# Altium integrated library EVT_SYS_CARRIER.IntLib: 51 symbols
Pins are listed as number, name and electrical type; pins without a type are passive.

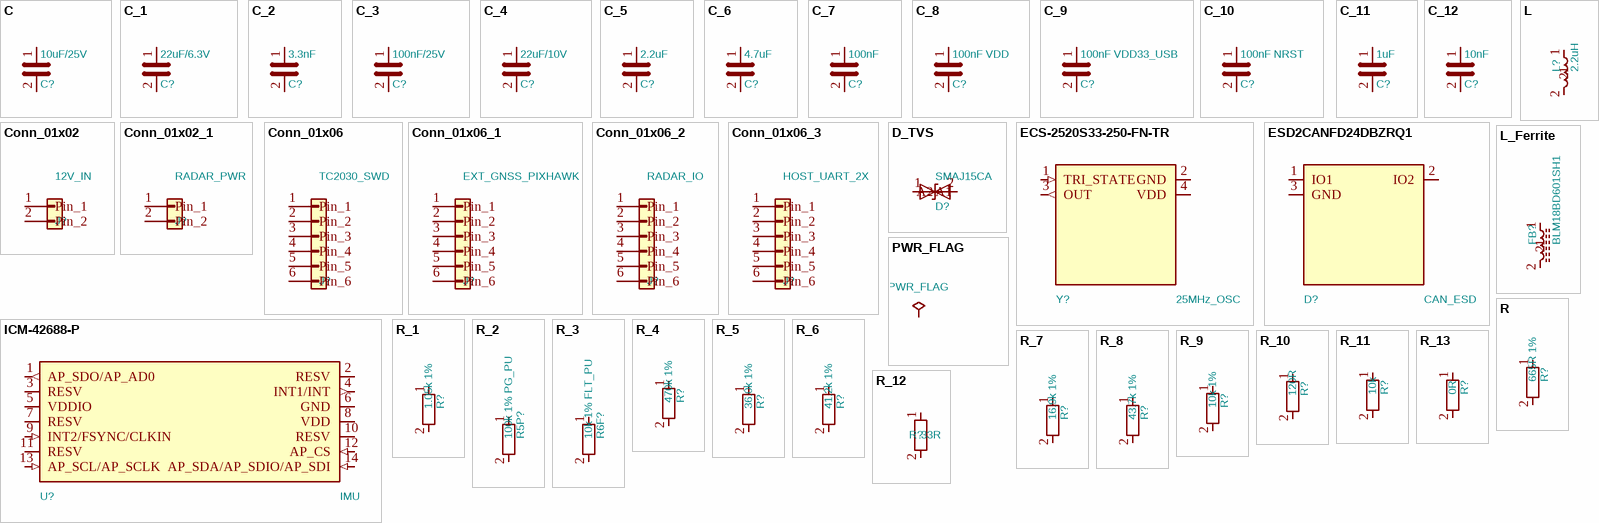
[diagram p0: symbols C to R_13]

## C
designator C?, comment 10uF/25V
MPN: 10uF_25V_X7R; hierarchy_path: /9ce958f3-6019-45fe-bc02-0cccce48adf8/8ef865ad-b15f-47f6-9f00-bb693d917fe2
footprint C_1206_3216Metric
pins: 1, 2

## C_1
designator C?, comment 22uF/6.3V
MPN: 22uF_6.3V_X7R; hierarchy_path: /9ce958f3-6019-45fe-bc02-0cccce48adf8/8ef865ad-b15f-47f6-9f00-bb693d917fe2
footprint C_1206_3216Metric
pins: 1, 2

## C_2
designator C?, comment 3.3nF
MPN: 3.3nF_X7R; hierarchy_path: /9ce958f3-6019-45fe-bc02-0cccce48adf8/8ef865ad-b15f-47f6-9f00-bb693d917fe2
footprint C_0603_1608Metric
pins: 1, 2

## C_3
designator C?, comment 100nF/25V
MPN: 100nF_25V_X7R; hierarchy_path: /9ce958f3-6019-45fe-bc02-0cccce48adf8/8ef865ad-b15f-47f6-9f00-bb693d917fe2
footprint C_0603_1608Metric
pins: 1, 2

## C_4
designator C?, comment 22uF/10V
MPN: 22uF_10V_X7R; hierarchy_path: /9ce958f3-6019-45fe-bc02-0cccce48adf8/8ef865ad-b15f-47f6-9f00-bb693d917fe2
footprint C_1206_3216Metric
pins: 1, 2

## C_5
designator C?, comment 2.2uF
MPN: 2.2uF_6.3V_X7R; hierarchy_path: /9ce958f3-6019-45fe-bc02-0cccce48adf8/eca40e6c-42e8-40ce-997d-d3259c6d70bc
footprint C_0603_1608Metric
pins: 1, 2

## C_6
designator C?, comment 4.7uF
MPN: 4.7uF_6.3V_X7R; hierarchy_path: /9ce958f3-6019-45fe-bc02-0cccce48adf8/eca40e6c-42e8-40ce-997d-d3259c6d70bc
footprint C_0805_2012Metric
pins: 1, 2

## C_7
designator C?, comment 100nF
MPN: 100nF_6.3V_X7R; hierarchy_path: /9ce958f3-6019-45fe-bc02-0cccce48adf8/eca40e6c-42e8-40ce-997d-d3259c6d70bc
footprint C_0402_1005Metric
pins: 1, 2

## C_8
designator C?, comment 100nF VDD
MPN: 100nF_6.3V_X7R; Decouples_U1_Pin: 15; hierarchy_path: /9ce958f3-6019-45fe-bc02-0cccce48adf8/eca40e6c-42e8-40ce-997d-d3259c6d70bc
footprint C_0402_1005Metric
pins: 1, 2

## C_9
designator C?, comment 100nF VDD33_USB
MPN: 100nF_6.3V_X7R; Decouples_U1_Pin: 114; hierarchy_path: /9ce958f3-6019-45fe-bc02-0cccce48adf8/eca40e6c-42e8-40ce-997d-d3259c6d70bc
footprint C_0402_1005Metric
pins: 1, 2

## C_10
designator C?, comment 100nF NRST
MPN: 100nF_6.3V_X7R; Filters_U1_Pin: 31; hierarchy_path: /9ce958f3-6019-45fe-bc02-0cccce48adf8/eca40e6c-42e8-40ce-997d-d3259c6d70bc
footprint C_0402_1005Metric
pins: 1, 2

## C_11
designator C?, comment 1uF
MPN: 1uF_6.3V_X7R; hierarchy_path: /9ce958f3-6019-45fe-bc02-0cccce48adf8/eca40e6c-42e8-40ce-997d-d3259c6d70bc
footprint C_0603_1608Metric
pins: 1, 2

## C_12
designator C?, comment 10nF
MPN: 10nF_6.3V_X7R; hierarchy_path: /9ce958f3-6019-45fe-bc02-0cccce48adf8/241b9f8d-0f6d-4c6e-8897-d9638f4bbe65
footprint C_0402_1005Metric
pins: 1, 2

## Conn_01x02
designator J?, comment 12V_IN
MPN: 43650-0200; hierarchy_path: /9ce958f3-6019-45fe-bc02-0cccce48adf8/8ef865ad-b15f-47f6-9f00-bb693d917fe2
footprint Molex_43650-0200_RA_THT_2P
pins: 1 Pin_1, 2 Pin_2

## Conn_01x02_1
designator J?, comment RADAR_PWR
MPN: 43650-0200; hierarchy_path: /9ce958f3-6019-45fe-bc02-0cccce48adf8/4586aff2-28b2-41d1-b1d0-d420a17fa486
footprint Molex_43650-0200_RA_THT_2P
pins: 1 Pin_1, 2 Pin_2

## Conn_01x06
designator J?, comment TC2030_SWD
MPN: TC2030-NL_TARGET; hierarchy_path: /9ce958f3-6019-45fe-bc02-0cccce48adf8/eca40e6c-42e8-40ce-997d-d3259c6d70bc
footprint TagConnect_TC2030_NL
pins: 1 Pin_1, 2 Pin_2, 3 Pin_3, 4 Pin_4, 5 Pin_5, 6 Pin_6

## Conn_01x06_1
designator J?, comment EXT_GNSS_PIXHAWK
MPN: SM06B-GHS-TB(LF)(SN); hierarchy_path: /9ce958f3-6019-45fe-bc02-0cccce48adf8/f1a35d3c-9d0c-4b86-b39c-b974cbb805b6
footprint JST_GH_SM06B-GHS-TB_1x06-1MP_P1.25mm_Horizontal
pins: 1 Pin_1, 2 Pin_2, 3 Pin_3, 4 Pin_4, 5 Pin_5, 6 Pin_6

## Conn_01x06_2
designator J?, comment RADAR_IO
MPN: 43045-0600; hierarchy_path: /9ce958f3-6019-45fe-bc02-0cccce48adf8/4586aff2-28b2-41d1-b1d0-d420a17fa486
footprint Molex_43045-0600_RA_THT_6P
pins: 1 Pin_1, 2 Pin_2, 3 Pin_3, 4 Pin_4, 5 Pin_5, 6 Pin_6

## Conn_01x06_3
designator J?, comment HOST_UART_2X
MPN: 43045-0600; hierarchy_path: /9ce958f3-6019-45fe-bc02-0cccce48adf8/2832ddd1-de9d-48ab-8137-5ba09d30c47d
footprint Molex_43045-0600_RA_THT_6P
pins: 1 Pin_1, 2 Pin_2, 3 Pin_3, 4 Pin_4, 5 Pin_5, 6 Pin_6

## D_TVS
designator D?, comment SMAJ15CA
hierarchy_path: /9ce958f3-6019-45fe-bc02-0cccce48adf8/8ef865ad-b15f-47f6-9f00-bb693d917fe2
footprint D_SMA
pins: 1 A1, 2 A2

## ECS-2520S33-250-FN-TR
designator Y?, comment 25MHz_OSC
MPN: ECS-2520S33-250-FN-TR; Capture_Status: LOCAL_CONTRACT_SYMBOL; hierarchy_path: /9ce958f3-6019-45fe-bc02-0cccce48adf8/eca40e6c-42e8-40ce-997d-d3259c6d70bc
footprint Oscillator_SMD_ECS_2520MV-xxx-xx-4Pin_2.5x2.0mm
pins: 1 TRI_STATE (in), 2 GND (power), 3 OUT (out), 4 VDD (power)

## ESD2CANFD24DBZRQ1
designator D?, comment CAN_ESD
MPN: ESD2CANFD24DBZRQ1; Capture_Status: LOCAL_CONTRACT_SYMBOL; hierarchy_path: /9ce958f3-6019-45fe-bc02-0cccce48adf8/4586aff2-28b2-41d1-b1d0-d420a17fa486
footprint SOT-23
pins: 1 IO1 (io), 2 IO2 (io), 3 GND

## ICM-42688-P
designator U?, comment IMU
MPN: ICM-42688-P; Capture_Status: LOCAL_CONTRACT_SYMBOL; hierarchy_path: /9ce958f3-6019-45fe-bc02-0cccce48adf8/241b9f8d-0f6d-4c6e-8897-d9638f4bbe65
footprint ICM-42688-P_LGA14_2.5x3mm_P0.5mm
pins: 1 AP_SDO/AP_AD0 (out), 2 RESV, 3 RESV, 4 INT1/INT (out), 5 VDDIO (power), 6 GND (power), 7 RESV, 8 VDD (power), 9 INT2/FSYNC/CLKIN (in), 10 RESV, 11 RESV, 12 AP_CS (in), 13 AP_SCL/AP_SCLK (in), 14 AP_SDA/AP_SDIO/AP_SDI (in)

## L
designator L?, comment 2.2uH
MPN: XFL4020-222MEC; hierarchy_path: /9ce958f3-6019-45fe-bc02-0cccce48adf8/8ef865ad-b15f-47f6-9f00-bb693d917fe2
footprint Coilcraft_XFL4020_4x4
pins: 1, 2

## L_Ferrite
designator FB?, comment BLM18BD601SH1
hierarchy_path: /9ce958f3-6019-45fe-bc02-0cccce48adf8/eca40e6c-42e8-40ce-997d-d3259c6d70bc
footprint L_0603_1608Metric
pins: 1, 2

## PWR_FLAG
designator #FLG?  (graphical)
hierarchy_path: /9ce958f3-6019-45fe-bc02-0cccce48adf8/8ef865ad-b15f-47f6-9f00-bb693d917fe2
pins: 1 (power)

## R
designator R?, comment 665R 1%
MPN: 665R_1%; hierarchy_path: /9ce958f3-6019-45fe-bc02-0cccce48adf8/8ef865ad-b15f-47f6-9f00-bb693d917fe2
footprint R_0603_1608Metric
pins: 1, 2

## R_1
designator R?, comment 1.05k 1%
MPN: 1.05k_1%; hierarchy_path: /9ce958f3-6019-45fe-bc02-0cccce48adf8/8ef865ad-b15f-47f6-9f00-bb693d917fe2
footprint R_0603_1608Metric
pins: 1, 2

## R_2
designator R5P?, comment 100k 1% PG_PU
MPN: 100k_1%; hierarchy_path: /9ce958f3-6019-45fe-bc02-0cccce48adf8/8ef865ad-b15f-47f6-9f00-bb693d917fe2
footprint R_0603_1608Metric
pins: 1, 2

## R_3
designator R6F?, comment 10k 1% FLT_PU
MPN: 10k_1%; hierarchy_path: /9ce958f3-6019-45fe-bc02-0cccce48adf8/8ef865ad-b15f-47f6-9f00-bb693d917fe2
footprint R_0603_1608Metric
pins: 1, 2

## R_4
designator R?, comment 470k 1%
MPN: 470k_1%; hierarchy_path: /9ce958f3-6019-45fe-bc02-0cccce48adf8/8ef865ad-b15f-47f6-9f00-bb693d917fe2
footprint R_0603_1608Metric
pins: 1, 2

## R_5
designator R?, comment 36.0k 1%
MPN: 36.0k_1%; hierarchy_path: /9ce958f3-6019-45fe-bc02-0cccce48adf8/8ef865ad-b15f-47f6-9f00-bb693d917fe2
footprint R_0603_1608Metric
pins: 1, 2

## R_6
designator R?, comment 41.2k 1%
MPN: 41.2k_1%; hierarchy_path: /9ce958f3-6019-45fe-bc02-0cccce48adf8/8ef865ad-b15f-47f6-9f00-bb693d917fe2
footprint R_0603_1608Metric
pins: 1, 2

## R_7
designator R?, comment 16.9k 1%
MPN: 16.9k_1%; hierarchy_path: /9ce958f3-6019-45fe-bc02-0cccce48adf8/8ef865ad-b15f-47f6-9f00-bb693d917fe2
footprint R_0603_1608Metric
pins: 1, 2

## R_8
designator R?, comment 43.7k 1%
MPN: 43.7k_1%; hierarchy_path: /9ce958f3-6019-45fe-bc02-0cccce48adf8/8ef865ad-b15f-47f6-9f00-bb693d917fe2
footprint R_0603_1608Metric
pins: 1, 2

## R_9
designator R?, comment 10k 1%
MPN: 10k_1%; hierarchy_path: /9ce958f3-6019-45fe-bc02-0cccce48adf8/eca40e6c-42e8-40ce-997d-d3259c6d70bc
footprint R_0603_1608Metric
pins: 1, 2

## R_10
designator R?, comment 120R
MPN: 120R_1%; hierarchy_path: /9ce958f3-6019-45fe-bc02-0cccce48adf8/4586aff2-28b2-41d1-b1d0-d420a17fa486
footprint R_0603_1608Metric
pins: 1, 2

## R_11
designator R?, comment 10k
MPN: 10k_1%; hierarchy_path: /9ce958f3-6019-45fe-bc02-0cccce48adf8/4586aff2-28b2-41d1-b1d0-d420a17fa486
footprint R_0603_1608Metric
pins: 1, 2

## R_12
designator R?, comment 33R
MPN: 33R_1%; hierarchy_path: /9ce958f3-6019-45fe-bc02-0cccce48adf8/2832ddd1-de9d-48ab-8137-5ba09d30c47d
footprint R_0402_1005Metric
pins: 1, 2

## R_13
designator R?, comment 0R
hierarchy_path: /9ce958f3-6019-45fe-bc02-0cccce48adf8/6cb1464a-bb78-4666-9d5a-fa6b793f4d4c
footprint R_0603_1608Metric
pins: 1, 2

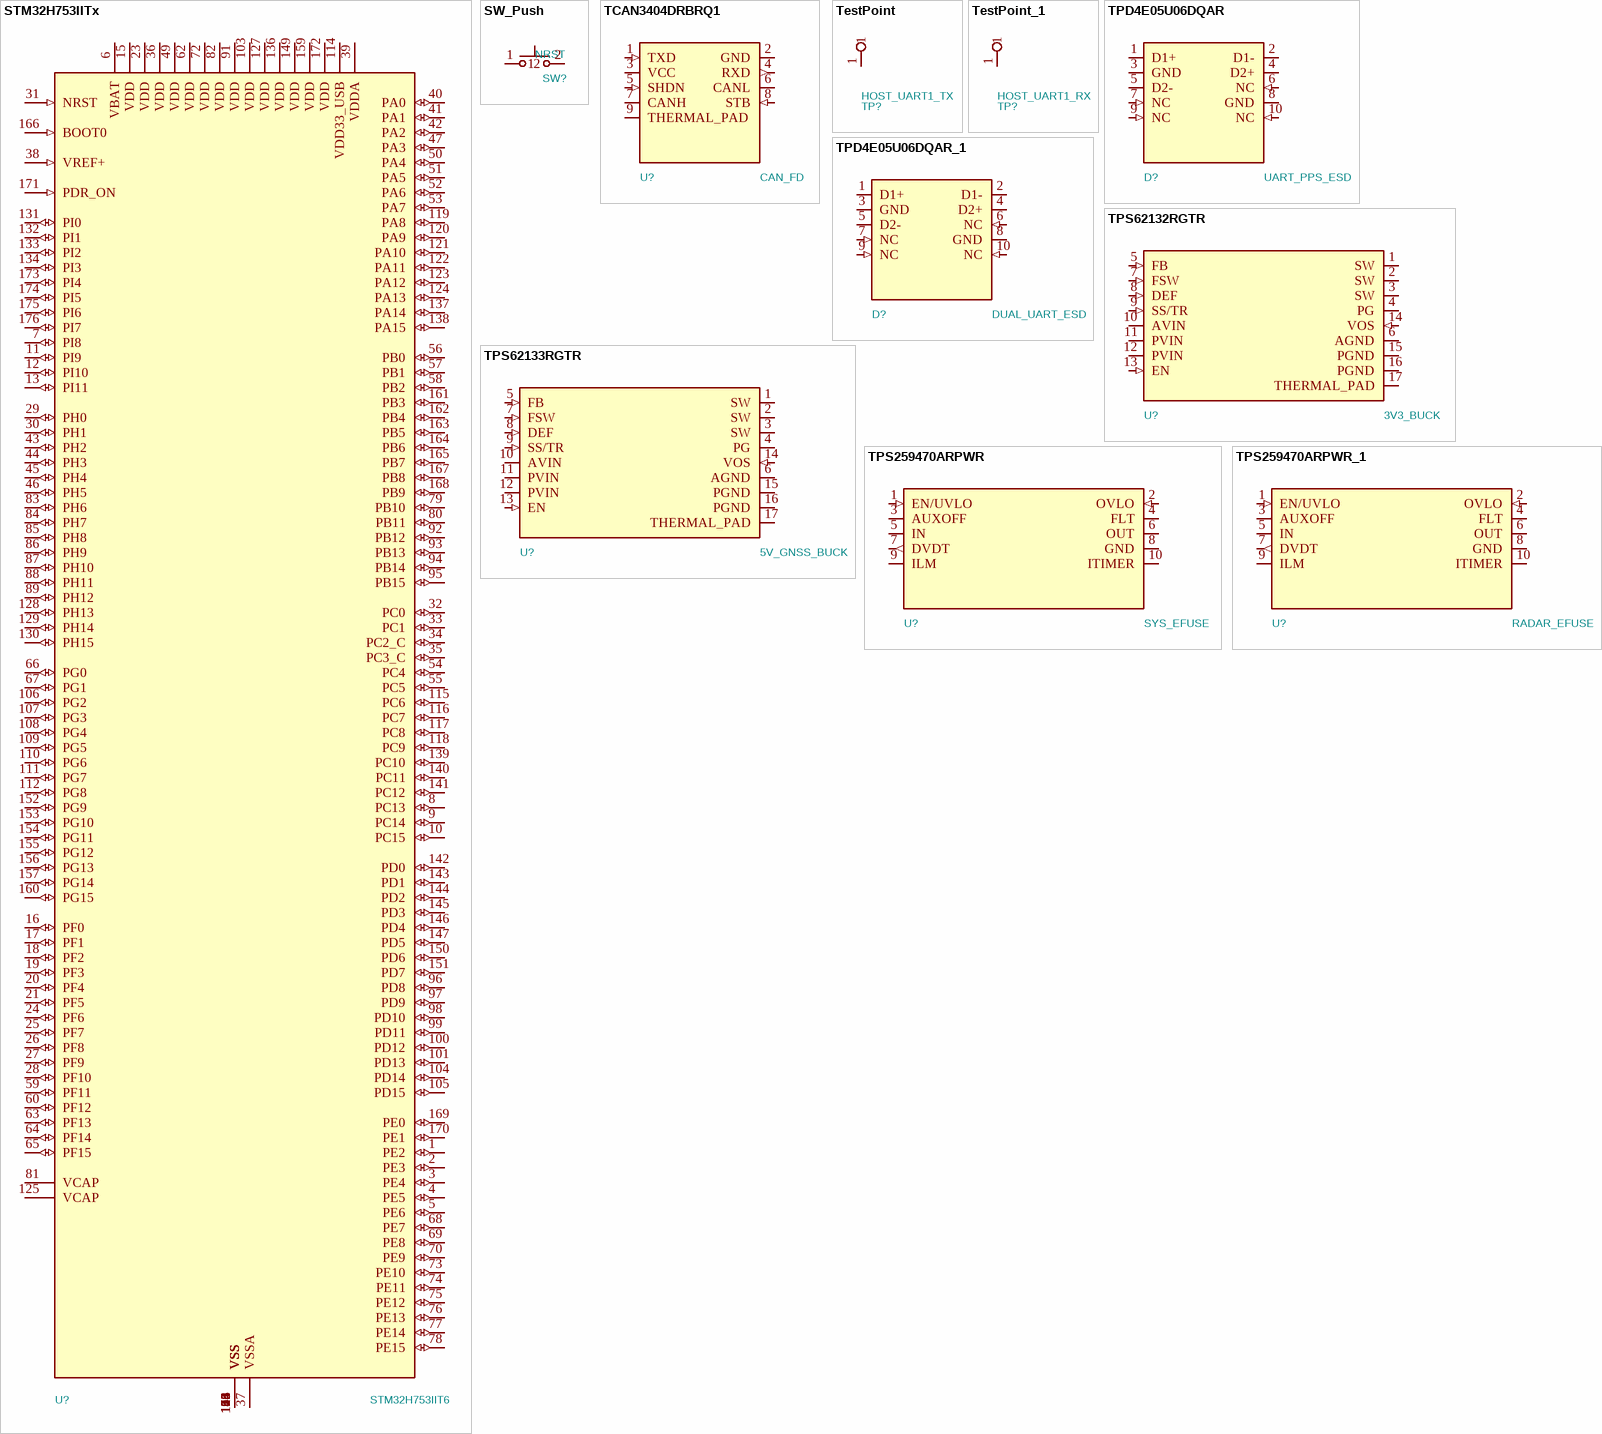
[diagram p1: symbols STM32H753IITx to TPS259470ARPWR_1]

## STM32H753IITx
designator U?, comment STM32H753IIT6
hierarchy_path: /9ce958f3-6019-45fe-bc02-0cccce48adf8/eca40e6c-42e8-40ce-997d-d3259c6d70bc
footprint LQFP-176_24x24mm_P0.5mm
pins: 1 PE2 (io), 2 PE3 (io), 3 PE4 (io), 4 PE5 (io), 5 PE6 (io), 6 VBAT (power), 7 PI8 (io), 8 PC13 (io), 9 PC14 (io), 10 PC15 (io), 11 PI9 (io), 12 PI10 (io), 13 PI11 (io), 14 VSS (power), 15 VDD (power), 16 PF0 (io), 17 PF1 (io), 18 PF2 (io), 19 PF3 (io), 20 PF4 (io), 21 PF5 (io), 22 VSS, 23 VDD (power), 24 PF6 (io), 25 PF7 (io), 26 PF8 (io), 27 PF9 (io), 28 PF10 (io), 29 PH0 (io), 30 PH1 (io), 31 NRST (in), 32 PC0 (io), 33 PC1 (io), 34 PC2_C (io), 35 PC3_C (io), 36 VDD (power), 37 VSSA (power), 38 VREF+ (in), 39 VDDA (power), 40 PA0 (io), 41 PA1 (io), 42 PA2 (io), 43 PH2 (io), 44 PH3 (io), 45 PH4 (io), 46 PH5 (io), 47 PA3 (io), 48 VSS, 49 VDD (power), 50 PA4 (io), 51 PA5 (io), 52 PA6 (io), 53 PA7 (io), 54 PC4 (io), 55 PC5 (io), 56 PB0 (io), 57 PB1 (io), 58 PB2 (io), 59 PF11 (io), 60 PF12 (io), 61 VSS, 62 VDD (power), 63 PF13 (io), 64 PF14 (io), 65 PF15 (io), 66 PG0 (io), 67 PG1 (io), 68 PE7 (io), 69 PE8 (io), 70 PE9 (io), 71 VSS, 72 VDD (power), 73 PE10 (io), 74 PE11 (io), 75 PE12 (io), 76 PE13 (io), 77 PE14 (io), 78 PE15 (io), 79 PB10 (io), 80 PB11 (io), 81 VCAP (power), 82 VDD (power), 83 PH6 (io), 84 PH7 (io), 85 PH8 (io), 86 PH9 (io), 87 PH10 (io), 88 PH11 (io), 89 PH12 (io), 90 VSS, 91 VDD (power), 92 PB12 (io), 93 PB13 (io), 94 PB14 (io), 95 PB15 (io), 96 PD8 (io), 97 PD9 (io), 98 PD10 (io), 99 PD11 (io), 100 PD12 (io), 101 PD13 (io), 102 VSS, 103 VDD (power), 104 PD14 (io), 105 PD15 (io), 106 PG2 (io), 107 PG3 (io), 108 PG4 (io), 109 PG5 (io), 110 PG6 (io), 111 PG7 (io), 112 PG8 (io), 113 VSS, 114 VDD33_USB (power), 115 PC6 (io), 116 PC7 (io), 117 PC8 (io), 118 PC9 (io), 119 PA8 (io), 120 PA9 (io), 121 PA10 (io), 122 PA11 (io), 123 PA12 (io), 124 PA13 (io), 125 VCAP (power), 126 VSS, 127 VDD (power), 128 PH13 (io), 129 PH14 (io), 130 PH15 (io), 131 PI0 (io), 132 PI1 (io), 133 PI2 (io), 134 PI3 (io), 135 VSS, 136 VDD (power), 137 PA14 (io), 138 PA15 (io), 139 PC10 (io), 140 PC11 (io), 141 PC12 (io), 142 PD0 (io), 143 PD1 (io), 144 PD2 (io), 145 PD3 (io), 146 PD4 (io), 147 PD5 (io), 148 VSS, 149 VDD (power), 150 PD6 (io), 151 PD7 (io), 152 PG9 (io), 153 PG10 (io), 154 PG11 (io), 155 PG12 (io), 156 PG13 (io), 157 PG14 (io), 158 VSS, 159 VDD (power), 160 PG15 (io), 161 PB3 (io), 162 PB4 (io), 163 PB5 (io), 164 PB6 (io), 165 PB7 (io), 166 BOOT0 (in), 167 PB8 (io), 168 PB9 (io), 169 PE0 (io), 170 PE1 (io), 171 PDR_ON (in), 172 VDD (power), 173 PI4 (io), 174 PI5 (io), 175 PI6 (io), 176 PI7 (io)

## SW_Push
designator SW?, comment NRST
MPN: TL3301NF160QG; hierarchy_path: /9ce958f3-6019-45fe-bc02-0cccce48adf8/6cb1464a-bb78-4666-9d5a-fa6b793f4d4c
footprint ESwitch_TL3301_GullWing_6x6
pins: 1, 2

## TCAN3404DRBRQ1
designator U?, comment CAN_FD
MPN: TCAN3404DRBRQ1; Capture_Status: LOCAL_CONTRACT_SYMBOL; hierarchy_path: /9ce958f3-6019-45fe-bc02-0cccce48adf8/4586aff2-28b2-41d1-b1d0-d420a17fa486
footprint Texas_DRB0008A
pins: 1 TXD (in), 2 GND (power), 3 VCC (power), 4 RXD (out), 5 SHDN (in), 6 CANL (io), 7 CANH (io), 8 STB (in), 9 THERMAL_PAD (power)

## TestPoint
designator TP?, comment HOST_UART1_TX
hierarchy_path: /9ce958f3-6019-45fe-bc02-0cccce48adf8/eca40e6c-42e8-40ce-997d-d3259c6d70bc
footprint TestPoint_Pad_D1.0mm
pins: 1

## TestPoint_1
designator TP?, comment HOST_UART1_RX
hierarchy_path: /9ce958f3-6019-45fe-bc02-0cccce48adf8/eca40e6c-42e8-40ce-997d-d3259c6d70bc
footprint TestPoint_Pad_D1.0mm
pins: 1

## TPD4E05U06DQAR
designator D?, comment UART_PPS_ESD
MPN: TPD4E05U06DQAR; Capture_Status: LOCAL_CONTRACT_SYMBOL; hierarchy_path: /9ce958f3-6019-45fe-bc02-0cccce48adf8/f1a35d3c-9d0c-4b86-b39c-b974cbb805b6
footprint USON-10_2.5x1.0mm_P0.5mm
pins: 1 D1+ (io), 2 D1- (io), 3 GND, 4 D2+ (io), 5 D2- (io), 6 NC (in), 7 NC (in), 8 GND, 9 NC (in), 10 NC (in)

## TPD4E05U06DQAR_1
designator D?, comment DUAL_UART_ESD
MPN: TPD4E05U06DQAR; Capture_Status: LOCAL_CONTRACT_SYMBOL; hierarchy_path: /9ce958f3-6019-45fe-bc02-0cccce48adf8/2832ddd1-de9d-48ab-8137-5ba09d30c47d
footprint USON-10_2.5x1.0mm_P0.5mm
pins: 1 D1+ (io), 2 D1- (io), 3 GND, 4 D2+ (io), 5 D2- (io), 6 NC (in), 7 NC (in), 8 GND, 9 NC (in), 10 NC (in)

## TPS62132RGTR
designator U?, comment 3V3_BUCK
MPN: TPS62132RGTR; Capture_Status: LOCAL_CONTRACT_SYMBOL; hierarchy_path: /9ce958f3-6019-45fe-bc02-0cccce48adf8/8ef865ad-b15f-47f6-9f00-bb693d917fe2
footprint VQFN-16-1EP_3x3mm_P0.5mm_EP1.68x1.68mm
pins: 1 SW, 2 SW, 3 SW, 4 PG (oc), 5 FB (in), 6 AGND (power), 7 FSW (in), 8 DEF (in), 9 SS/TR (in), 10 AVIN (power), 11 PVIN (power), 12 PVIN (power), 13 EN (in), 14 VOS (in), 15 PGND (power), 16 PGND (power), 17 THERMAL_PAD (power)

## TPS62133RGTR
designator U?, comment 5V_GNSS_BUCK
MPN: TPS62133RGTR; Capture_Status: LOCAL_CONTRACT_SYMBOL; hierarchy_path: /9ce958f3-6019-45fe-bc02-0cccce48adf8/8ef865ad-b15f-47f6-9f00-bb693d917fe2
footprint VQFN-16-1EP_3x3mm_P0.5mm_EP1.68x1.68mm
pins: 1 SW, 2 SW, 3 SW, 4 PG (oc), 5 FB (in), 6 AGND (power), 7 FSW (in), 8 DEF (in), 9 SS/TR (in), 10 AVIN (power), 11 PVIN (power), 12 PVIN (power), 13 EN (in), 14 VOS (in), 15 PGND (power), 16 PGND (power), 17 THERMAL_PAD (power)

## TPS259470ARPWR
designator U?, comment SYS_EFUSE
MPN: TPS259470ARPWR; Capture_Status: LOCAL_CONTRACT_SYMBOL; hierarchy_path: /9ce958f3-6019-45fe-bc02-0cccce48adf8/8ef865ad-b15f-47f6-9f00-bb693d917fe2
footprint TPS259470A_RPW0010A_VQFN-HR-10_2x2mm_P0.475mm
pins: 1 EN/UVLO (in), 2 OVLO (in), 3 AUXOFF (oc), 4 FLT (oc), 5 IN (power), 6 OUT (power), 7 DVDT (out), 8 GND (power), 9 ILM (io), 10 ITIMER (io)

## TPS259470ARPWR_1
designator U?, comment RADAR_EFUSE
MPN: TPS259470ARPWR; Capture_Status: LOCAL_CONTRACT_SYMBOL; hierarchy_path: /9ce958f3-6019-45fe-bc02-0cccce48adf8/8ef865ad-b15f-47f6-9f00-bb693d917fe2
footprint TPS259470A_RPW0010A_VQFN-HR-10_2x2mm_P0.475mm
pins: 1 EN/UVLO (in), 2 OVLO (in), 3 AUXOFF (oc), 4 FLT (oc), 5 IN (power), 6 OUT (power), 7 DVDT (out), 8 GND (power), 9 ILM (io), 10 ITIMER (io)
